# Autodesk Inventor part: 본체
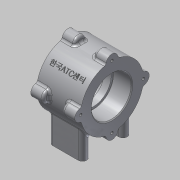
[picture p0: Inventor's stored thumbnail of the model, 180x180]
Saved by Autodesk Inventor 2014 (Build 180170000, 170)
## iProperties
Created: 2015-03
Part Number: 본체
Material: 알루미늄 6061
Document SubType Name: Modeling
Designer: MYHOME
Mass: 450.775 g
Surface Area: 332.736 cm^2
Volume: 166.338 cm^3
Density: 2.71 g/cm^3
Appearance: 알루미늄 - 평지
Author: MYHOME
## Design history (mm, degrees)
sketch "스케치2"
  geometry: C1 r 37 at (0, 0); 1 further point
  constraints: 1 centre point, 1 coincident
  dimensions: "d0" = 74 diameter of C1
extrude "돌출1" new body sketch "스케치2" stored distance "d1" = 52; taper "d2" = 0 deg
sketch "스케치3"
  geometry: C1 r 7 at (0, 37); C2 r 7 at (37, 0); C3 r 7 at (0, -37); C4 r 7 at (-37, 0); A1 r 37 centre (0, 0) between (0, 37) and (37, 0) reference
  constraints: 4 centre point, 4 point on circle, 2 horizontal alignment, 2 vertical alignment
  dimensions: "d3" = 7 radius of C1; "d4" = 7 radius of C2; "d5" = 7 radius of C3; "d6" = 7 radius of C4
extrude "돌출2" join sketch "스케치3" distance "d7" = 15; taper "d8" = 0 deg
sketch "스케치4"
  geometry: A1 r 7 centre (0, -37) between (-6.969, -36.338) and (6.969, -36.338) reference; A2 r 7 centre (37, 0) between (36.338, -6.969) and (36.338, 6.969) reference; A3 r 7 centre (0, 37) between (6.969, 36.338) and (-6.969, 36.338) reference; A4 r 7 centre (-37, 0) between (-36.338, 6.969) and (-36.338, -6.969) reference; 4 further points
  constraints: 4 coincident
hole "구멍1" sketch "스케치4" at (0, 37), (37, 0), (0, -37), (-37, 0) diameter "d9" = 3.242; stored, may be unused: countersink angle "d13" = 90 deg, drill point angle "d15" = 118 deg; dims "d10" = 8, "d11" = 4, "d12" = 2, "d14" = 11
node "작업 평면1"
sketch "스케치5"
  geometry: L1 (-15, 24)-(15, 24); L2 (-15, 19)-(15, 19); L3 (15, 29)-(-15, 29); L4 (-15, -24)-(15, -24); L5 (-15, -29)-(15, -29); L6 (15, -19)-(-15, -19); A1 r 5 centre (-15, 24) between (-15, 29) and (-15, 19); A2 r 5 centre (15, 24) between (15, 19) and (15, 29); A3 r 5 centre (-15, -24) between (-15, -19) and (-15, -29); A4 r 5 centre (15, -24) between (15, -29) and (15, -19); 3 further points
  constraints: 16 end point, 8 point on circle, 8 tangent, 4 centre point, 4 parallel, 2 midpoint, 2 vertical alignment, 1 equal radius, 1 horizontal
  dimensions: "d18" = 10 distance between parallel lines of L3 L2; "d19" = 24 distance of point (0, -24) point (0, 0); "d20" = 48 distance of point (0, 24) point (0, -24); "d21" = 40 dimension on A3 A4
extrude "돌출3" join sketch "스케치5" stored distance "d22" = 15; taper "d23" = 0 deg
sketch "스케치6"
  geometry: L1 (15, -29)-(-15, -29) reference; L2 (-15, -19)-(15, -19) reference; A1 r 5 centre (15, 24) between (15, 19) and (15, 29) reference; A2 r 5 centre (-15, 24) between (-15, 29) and (-15, 19) reference; A3 r 5 centre (15, -24) between (15, -29) and (15, -19) reference; A4 r 5 centre (-15, -24) between (-15, -19) and (-15, -29) reference; 5 further points
  constraints: 4 coincident
hole "구멍2" sketch "스케치6" at (-15, 24), (15, 24), (15, -24), (-15, -24) diameter "d24" = 4.134; stored, may be unused: countersink angle "d28" = 90 deg, drill point angle "d30" = 118 deg; dims "d25" = 6, "d26" = 4, "d27" = 2, "d29" = 8
sketch "스케치7"
  geometry: C1 r 23.5 at (0, 0); A1 r 37 centre (0, 0) between (-6.969, 36.338) and (-36.338, 6.969) reference
  constraints: 1 centre point, 1 coincident
  dimensions: "d31" = 47 diameter of C1
extrude "돌출4" cut sketch "스케치7" distance "d32" = 22; taper "d33" = 0 deg
hole "구멍3" diameter "d36" = 42; stored, may be unused: countersink angle "d40" = 90 deg, drill point angle "d42" = 0 deg; dims "d34" = 10, "d35" = 10, "d37" = 6, "d38" = 47, "d39" = 22, "d41" = 8
chamfer "모따기1" distance "d43" = 1; stored, may be unused: second distance "d44" = 2, angle "d45" = 45 deg
fillet "모깎기1" dims "d46" = 0.3
fillet "모깎기2" dims "d47" = 3
fillet "모깎기3" dims "d48" = 3
sketch "스케치8"
  geometry: L1 (0, 0)-(-45.449, 0); L2 (0, 0)-(-26.517, 26.517); L3 (-26.517, 26.517)-(-39.775, 13.258)
  constraints: 6 end point, 1 coincident, 1 horizontal, 1 perpendicular
  dimensions: "d49" = 45 deg angle of L2 L1; "d50" = 37.5 distance of L1.start L2.end
node "작업 평면2"
sketch "스케치9"
  geometry: 2 further points
  constraints: 2 coincident, 1 other
feature "엠보싱1" sketch "스케치9" dims "d52" = 0.5, "d53" = 0
node "솔리드1"
mirror "대칭1"
node "투영된 루프1"
other parameters: "d16" = -56, "d51" = 90 deg
